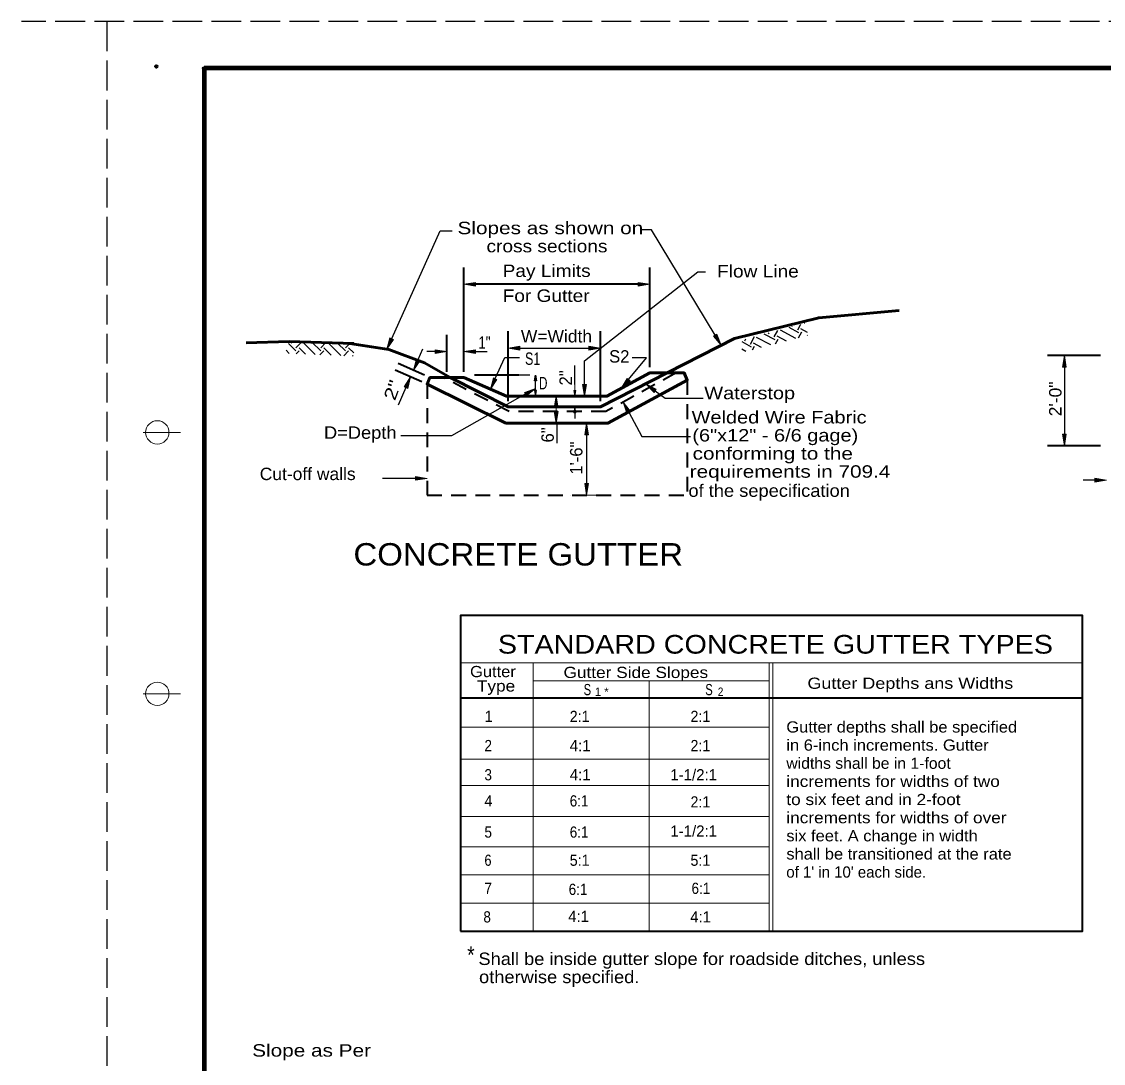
# Model space of a CAD drawing. Extents: x 72.6 to 107.3, y 36.1 to 58.1.
# Drawn here: x 72.62 to 84.21, y 46.92 to 58.08 of the extents above; entities that cross this region are included whole.
import ezdxf

# ---------------------------------------------------------------- set-up
doc = ezdxf.new("R2010")
doc.units = 0
doc.header["$LTSCALE"] = 0.053
doc.header["$PDMODE"] = 32
doc.header["$PDSIZE"] = 0.0265
doc.linetypes.add('LONG_DASHED', pattern=[7.5, 6, -1.5])
doc.linetypes.add('MEDIUM_DASHED', pattern=[4.5, 3, -1.5])
for name, color, linetype, lineweight in [('1', 7, 'Continuous', 35), ('2', 7, 'MEDIUM_DASHED', 35), ('3', 7, 'Continuous', 13), ('6', 7, 'Continuous', 13)]:
    doc.layers.add(name, color=color, linetype=linetype, lineweight=lineweight)

msp = doc.modelspace()

# ---------------------------------------------------------------- hatches: boundary and pattern name
at = {"layer": '1'}
for points in [[(77.48683, 55.24517), (77.48683, 55.28683), (77.36183, 55.266), (77.36183, 55.266)], [(79.23108, 55.24517), (79.23108, 55.28683), (79.35608, 55.266), (79.35608, 55.266)], [(77.96333, 54.56225), (77.96333, 54.60392), (77.83833, 54.58308), (77.83833, 54.58308)], [(78.70275, 54.56225), (78.70275, 54.60392), (78.82775, 54.58308), (78.82775, 54.58308)], [(76.89275, 54.45125), (76.85458, 54.468), (76.82333, 54.34517), (76.82333, 54.34517)], [(83.81583, 54.37842), (83.77408, 54.37842), (83.795, 54.50342), (83.795, 54.50342)], [(76.761, 54.15175), (76.72283, 54.1685), (76.79225, 54.2745), (76.79225, 54.2745)], [(78.13983, 54.23092), (78.119, 54.23092), (78.12942, 54.29342), (78.12942, 54.29342)], [(78.13983, 54.12917), (78.119, 54.12917), (78.12942, 54.06667), (78.12942, 54.06667)], [(78.56175, 54.12917), (78.54092, 54.12917), (78.55133, 54.06667), (78.55133, 54.06667)], [(78.372, 53.94167), (78.33033, 53.94167), (78.35117, 54.06667), (78.35117, 54.06667)], [(78.372, 53.90358), (78.33033, 53.90358), (78.35117, 53.77858), (78.35117, 53.77858)], [(78.56175, 53.89008), (78.54092, 53.89008), (78.55133, 53.95258), (78.55133, 53.95258)], [(78.69833, 53.65358), (78.65667, 53.65358), (78.6775, 53.77858), (78.6775, 53.77858)], [(83.81583, 53.65967), (83.77408, 53.65967), (83.795, 53.53467), (83.795, 53.53467)], [(78.69833, 53.13175), (78.65667, 53.13175), (78.6775, 53.00675), (78.6775, 53.00675)], [(84.12108, 53.14683), (84.12108, 53.1885), (84.24608, 53.16758), (84.24608, 53.16758)]]:
    msp.add_hatch(color=256, dxfattribs=at).paths.add_polyline_path(points)
at = {"layer": '3'}
for points in [[(80.072, 54.73067), (80.03633, 54.70917), (80.11867, 54.61283), (80.11867, 54.61283)], [(76.60825, 54.67558), (76.57025, 54.69267), (76.53808, 54.57008), (76.53808, 54.57008)], [(77.0555, 54.52408), (77.0555, 54.56575), (77.1805, 54.54492), (77.1805, 54.54492)], [(77.48683, 54.52408), (77.48683, 54.56575), (77.36183, 54.54492), (77.36183, 54.54492)], [(77.71708, 54.2475), (77.67908, 54.26467), (77.64675, 54.14208), (77.64675, 54.14208)], [(79.14242, 54.23167), (79.11033, 54.25833), (79.0465, 54.14883), (79.0465, 54.14883)], [(78.01033, 54.10767), (78.03083, 54.07142), (78.12942, 54.151), (78.12942, 54.151)], [(78.67658, 54.19167), (78.63492, 54.19167), (78.65575, 54.06667), (78.65575, 54.06667)], [(79.39933, 54.10883), (79.42408, 54.14233), (79.31117, 54.19983), (79.31117, 54.19983)], [(79.10992, 53.885), (79.14658, 53.90483), (79.06875, 54.00492), (79.06875, 54.00492)], [(76.84317, 53.20833), (76.84317, 53.16667), (76.96817, 53.1875), (76.96817, 53.1875)]]:
    msp.add_hatch(color=256, dxfattribs=at).paths.add_polyline_path(points)

# ---------------------------------------------------------------- linework, layer by layer
at = {"layer": '1', "linetype": 'LONG_DASHED', "lineweight": 25}
for p, q in [((107.16175, 58.07983), (72.62475, 58.07983)), ((73.53675, 58.07983), (73.53675, 36.07983))]:
    msp.add_line(p, q, dxfattribs=at)
at = {"layer": '1', "lineweight": 158}
for p, q in [((74.57842, 57.57983), (74.57842, 36.57983)), ((107.07842, 57.57983), (74.57842, 57.57983))]:
    msp.add_line(p, q, dxfattribs=at)
at = {"layer": '1'}
for p, q in [((77.36183, 54.33033), (77.36183, 55.446)), ((79.35608, 54.37925), (79.35608, 55.446)), ((79.23108, 55.266), (77.48683, 55.266)), ((77.83833, 54.01508), (77.83833, 54.76308)), ((78.82775, 54.01508), (78.82775, 54.76308)), ((84.18358, 54.50342), (83.615, 54.50342)), ((76.942, 54.293), (76.65858, 54.41767)), ((76.91092, 54.22233), (76.6275, 54.347)), ((84.18358, 53.53467), (83.615, 53.53467)), ((77.32617, 50.836), (83.98917, 50.836))]:
    msp.add_line(p, q, dxfattribs=at)
at = {"layer": '1', "lineweight": 25}
for p, q in [((80.94175, 54.7785), (80.97342, 54.83742)), ((81.01333, 54.84642), (81.01142, 54.8475)), ((80.43375, 54.62625), (80.47658, 54.70592)), ((80.65042, 54.616), (80.49875, 54.69767)), ((80.69725, 54.67067), (80.58067, 54.73342)), ((80.62575, 54.73575), (80.63192, 54.747)), ((80.68775, 54.70242), (80.725, 54.77167)), ((80.81792, 54.65883), (80.7195, 54.71192)), ((80.91783, 54.68492), (80.75275, 54.77383)), ((80.95125, 54.74683), (80.84575, 54.80358)), ((80.87975, 54.81192), (80.88033, 54.81275)), ((80.94842, 54.69225), (80.983, 54.75633)), ((81.04183, 54.75125), (80.9735, 54.78808)), ((81.04108, 54.716), (81.04483, 54.723)), ((75.56342, 54.55242), (75.48217, 54.63358)), ((75.51367, 54.63525), (75.53108, 54.65258)), ((75.56342, 54.5855), (75.62733, 54.6495)), ((75.66442, 54.51767), (75.59658, 54.5855)), ((75.76808, 54.5135), (75.64625, 54.63525)), ((75.82858, 54.55242), (75.735, 54.646)), ((75.77883, 54.63525), (75.78792, 54.64425)), ((75.82858, 54.5855), (75.88417, 54.64117)), ((75.94083, 54.50642), (75.86175, 54.5855)), ((76.044, 54.50267), (75.91142, 54.63525)), ((76.09375, 54.55242), (76.009, 54.63708)), ((76.044, 54.63525), (76.04475, 54.63592)), ((76.09375, 54.5855), (76.141, 54.63283)), ((76.18183, 54.53058), (76.12692, 54.5855)), ((76.18183, 54.63), (76.18033, 54.63158)), ((77.96333, 54.58308), (78.70275, 54.58308)), ((80.44325, 54.5945), (80.34208, 54.64892)), ((80.37175, 54.65958), (80.3835, 54.68117)), ((80.45442, 54.56592), (80.475, 54.60408)), ((80.54992, 54.59025), (80.4655, 54.63575)), ((80.70142, 54.62908), (80.729, 54.68025)), ((75.49158, 54.52475), (75.45717, 54.55917)), ((75.56592, 54.52175), (75.59658, 54.55242)), ((75.82067, 54.51133), (75.86175, 54.55242)), ((76.07542, 54.50092), (76.12692, 54.55242)), ((76.171, 54.49708), (76.17658, 54.50267)), ((76.87367, 54.45958), (76.924, 54.574)), ((80.38233, 54.54742), (80.3395, 54.5705)), ((78.55133, 54.19167), (78.55133, 54.39708)), ((83.795, 54.37842), (83.795, 53.65967)), ((78.06983, 54.29342), (77.94942, 54.29342)), ((76.74192, 54.16008), (76.65842, 53.97025)), ((78.12942, 54.12917), (78.12942, 54.23092)), ((78.077, 54.06667), (77.94942, 54.06667)), ((78.55133, 53.89008), (78.55133, 53.82758)), ((78.56908, 53.77858), (78.8575, 53.77858)), ((78.6775, 53.65358), (78.6775, 53.13175)), ((84.12108, 53.16767), (83.99608, 53.16767))]:
    msp.add_line(p, q, dxfattribs=at)
at = {"layer": '1', "lineweight": 53}
for p, q in [((75.48908, 54.654), (75.0305, 54.63792)), ((76.18183, 54.6315), (75.48908, 54.654)), ((76.55892, 54.56683), (76.141, 54.63283))]:
    msp.add_line(p, q, dxfattribs=at)
at = {"layer": '1', "lineweight": 13}
for p, q in [((78.55133, 54.12917), (78.55133, 54.19167)), ((78.39292, 54.06667), (78.53117, 54.06667)), ((78.61233, 54.06667), (78.73133, 54.06667)), ((78.35117, 53.94167), (78.35117, 53.90358)), ((78.61383, 53.95258), (78.73133, 53.95258)), ((78.40333, 53.77858), (78.53117, 53.77858)), ((74.32842, 53.67983), (73.92842, 53.67983)), ((78.56908, 53.00675), (78.8575, 53.00675)), ((77.32617, 51.213), (83.98917, 51.213)), ((78.10642, 51.213), (78.10642, 48.33683)), ((80.632, 48.33683), (80.632, 51.213)), ((80.67308, 48.33683), (80.67308, 51.213)), ((78.10642, 51.01908), (80.632, 51.01908)), ((79.34867, 51.01908), (79.34867, 48.33683)), ((74.32842, 50.87983), (73.92842, 50.87983)), ((77.32617, 50.52358), (80.632, 50.52358)), ((77.32617, 50.17883), (80.632, 50.17883)), ((77.32617, 49.89875), (80.632, 49.89875)), ((77.32617, 49.56483), (80.632, 49.56483)), ((77.32617, 49.24158), (80.632, 49.24158)), ((77.32617, 48.94), (80.632, 48.94)), ((77.32617, 48.63842), (80.632, 48.63842))]:
    msp.add_line(p, q, dxfattribs=at)
for points in [[(77.48683, 55.24517), (77.48683, 55.28683), (77.36183, 55.266), (77.36183, 55.266)], [(79.23108, 55.24517), (79.23108, 55.28683), (79.35608, 55.266), (79.35608, 55.266)], [(77.96333, 54.56225), (77.96333, 54.60392), (77.83833, 54.58308), (77.83833, 54.58308)], [(78.70275, 54.56225), (78.70275, 54.60392), (78.82775, 54.58308), (78.82775, 54.58308)], [(76.89275, 54.45125), (76.85458, 54.468), (76.82333, 54.34517), (76.82333, 54.34517)], [(83.81583, 54.37842), (83.77408, 54.37842), (83.795, 54.50342), (83.795, 54.50342)], [(76.761, 54.15175), (76.72283, 54.1685), (76.79225, 54.2745), (76.79225, 54.2745)], [(78.56175, 54.12917), (78.54092, 54.12917), (78.55133, 54.06667), (78.55133, 54.06667)], [(78.372, 53.94167), (78.33033, 53.94167), (78.35117, 54.06667), (78.35117, 54.06667)], [(78.372, 53.90358), (78.33033, 53.90358), (78.35117, 53.77858), (78.35117, 53.77858)], [(78.56175, 53.89008), (78.54092, 53.89008), (78.55133, 53.95258), (78.55133, 53.95258)], [(78.69833, 53.65358), (78.65667, 53.65358), (78.6775, 53.77858), (78.6775, 53.77858)], [(83.81583, 53.65967), (83.77408, 53.65967), (83.795, 53.53467), (83.795, 53.53467)], [(78.69833, 53.13175), (78.65667, 53.13175), (78.6775, 53.00675), (78.6775, 53.00675)], [(84.12108, 53.14683), (84.12108, 53.1885), (84.24608, 53.16758), (84.24608, 53.16758)]]:
    msp.add_lwpolyline(points, close=True, dxfattribs=at)
at = {"layer": '1', "lineweight": 53}
for points in [[(80.2625, 54.68642), (81.16475, 54.908), (82.02408, 54.98392)], [(80.2625, 54.68642), (78.82775, 53.95258), (77.83833, 53.95258), (77.21675, 54.26783), (76.94225, 54.4255), (76.55892, 54.56683)]]:
    msp.add_lwpolyline(points, dxfattribs=at)
msp.add_lwpolyline([(77.8125, 53.77858), (78.90542, 53.77858), (79.75492, 54.24067), (79.72383, 54.31675), (79.35608, 54.31675), (78.89508, 54.06667), (77.81767, 54.06667), (77.36183, 54.26783), (76.99925, 54.26783), (76.96817, 54.19717)], close=True, dxfattribs=at)
at = {"layer": '1', "lineweight": 25}
for points in [[(78.13983, 54.23092), (78.119, 54.23092), (78.12942, 54.29342), (78.12942, 54.29342)], [(78.13983, 54.12917), (78.119, 54.12917), (78.12942, 54.06667), (78.12942, 54.06667)]]:
    msp.add_lwpolyline(points, close=True, dxfattribs=at)
at = {"layer": '1'}
msp.add_lwpolyline([(77.32617, 48.33683), (83.98917, 48.33683), (83.98917, 51.71933), (77.32617, 51.71933)], close=True, dxfattribs=at)
at = {"layer": '1', "lineweight": 13}
for centre in [(74.07842, 53.67983), (74.07842, 50.87983)]:
    msp.add_circle(centre, 0.125, dxfattribs=at)
at = {"layer": '1'}
for p in [(74.06642, 57.59983), (74.57842, 57.57983)]:
    msp.add_point(p, dxfattribs=at)
at = {"layer": '2'}
for p, q in [((79.75492, 54.24067), (79.75492, 53.00675)), ((76.96817, 54.19717), (76.96817, 53.00675)), ((76.96817, 53.00675), (79.75492, 53.00675))]:
    msp.add_line(p, q, dxfattribs=at)
msp.add_lwpolyline([(79.63575, 54.31675), (78.88467, 53.90367), (77.84875, 53.90367), (77.13908, 54.26783)], dxfattribs=at)
at = {"layer": '3', "lineweight": 35}
for p, q in [((77.1805, 54.33033), (77.1805, 54.72492)), ((77.94942, 54.29342), (77.47467, 54.29342))]:
    msp.add_line(p, q, dxfattribs=at)
at = {"layer": '3'}
for p, q in [((77.36183, 54.49833), (77.36183, 54.72492)), ((77.1805, 54.54492), (77.18058, 54.54492))]:
    msp.add_line(p, q, dxfattribs=at)
at = {"layer": '3', "lineweight": 25}
for p, q in [((77.0555, 54.54492), (76.96517, 54.54492)), ((77.48683, 54.54492), (77.61183, 54.54492)), ((79.41175, 54.12558), (79.52025, 54.0455)), ((79.52025, 54.0455), (79.92517, 54.0455)), ((78.35892, 53.77858), (78.35892, 53.56333)), ((76.84317, 53.1875), (76.48908, 53.1875))]:
    msp.add_line(p, q, dxfattribs=at)
for points in [[(76.58925, 54.68417), (77.10775, 55.8385), (77.23775, 55.8385)], [(80.05417, 54.71992), (79.37358, 55.85033), (79.26058, 55.85033)], [(78.65575, 54.19167), (78.65575, 54.44792), (79.86908, 55.39933), (79.94992, 55.39933)], [(77.69808, 54.25608), (77.79975, 54.48167), (77.95692, 54.48167)], [(79.12642, 54.245), (79.32017, 54.47825), (79.16417, 54.47825)], [(78.02058, 54.0895), (77.22858, 53.642), (76.6855, 53.642)], [(79.12825, 53.89492), (79.26817, 53.63592), (79.78917, 53.63592)]]:
    msp.add_lwpolyline(points, dxfattribs=at)
at = {"layer": '3'}
for points in [[(80.072, 54.73067), (80.03633, 54.70917), (80.11867, 54.61283), (80.11867, 54.61283)], [(76.60825, 54.67558), (76.57025, 54.69267), (76.53808, 54.57008), (76.53808, 54.57008)], [(77.0555, 54.52408), (77.0555, 54.56575), (77.1805, 54.54492), (77.1805, 54.54492)], [(77.48683, 54.52408), (77.48683, 54.56575), (77.36183, 54.54492), (77.36183, 54.54492)], [(77.71708, 54.2475), (77.67908, 54.26467), (77.64675, 54.14208), (77.64675, 54.14208)], [(79.14242, 54.23167), (79.11033, 54.25833), (79.0465, 54.14883), (79.0465, 54.14883)], [(78.01033, 54.10767), (78.03083, 54.07142), (78.12942, 54.151), (78.12942, 54.151)], [(78.67658, 54.19167), (78.63492, 54.19167), (78.65575, 54.06667), (78.65575, 54.06667)], [(79.39933, 54.10883), (79.42408, 54.14233), (79.31117, 54.19983), (79.31117, 54.19983)], [(79.10992, 53.885), (79.14658, 53.90483), (79.06875, 54.00492), (79.06875, 54.00492)], [(76.84317, 53.20833), (76.84317, 53.16667), (76.96817, 53.1875), (76.96817, 53.1875)]]:
    msp.add_lwpolyline(points, close=True, dxfattribs=at)
at = {"layer": '6'}
for p, q in [((77.36183, 55.266), (77.36192, 55.266)), ((78.82775, 54.58308), (78.82783, 54.58308)), ((77.36183, 54.43583), (77.36192, 54.43583)), ((76.82333, 54.34517), (76.82342, 54.34517)), ((76.99925, 54.26783), (76.99933, 54.26783)), ((77.1805, 54.26783), (77.18058, 54.26783)), ((77.36183, 54.26783), (77.36192, 54.26783)), ((79.35608, 54.31675), (79.35617, 54.31675)), ((76.96817, 54.19717), (76.96825, 54.19717)), ((78.33042, 54.06667), (78.3305, 54.06667)), ((78.54983, 54.06667), (78.54992, 54.06667)), ((78.55133, 54.06667), (78.55142, 54.06667)), ((77.83833, 53.95258), (77.83842, 53.95258)), ((78.55133, 53.95258), (78.55142, 53.95258)), ((78.82775, 53.95258), (78.82783, 53.95258)), ((78.34083, 53.77858), (78.34092, 53.77858)), ((78.35117, 53.77858), (78.35125, 53.77858)), ((78.50658, 53.77858), (78.50667, 53.77858)), ((83.795, 53.53467), (83.79508, 53.53467)), ((78.50658, 53.00675), (78.50667, 53.00675)), ((78.6775, 53.00675), (78.67758, 53.00675))]:
    msp.add_line(p, q, dxfattribs=at)
at = {"layer": '6', "lineweight": 25}
for p, q in [((78.12942, 54.29342), (78.1295, 54.29342)), ((78.13233, 54.29342), (78.13242, 54.29342)), ((78.1395, 54.06667), (78.13958, 54.06667))]:
    msp.add_line(p, q, dxfattribs=at)

# ---------------------------------------------------------------- texts
at = {"layer": '1', "width": 1.05}
msp.add_text('W=Width', height=0.133, dxfattribs=at).set_placement((77.97308, 54.64308))
at = {"layer": '1'}
for s, p in [('2"', (78.51933, 54.18267)), ('1\'-6"', (78.63208, 53.22725))]:
    msp.add_text(s, height=0.133, rotation=90, dxfattribs=at).set_placement(p)
at = {"layer": '1', "width": 1.05}
msp.add_text('2\'-0"', height=0.133, rotation=90, dxfattribs=at).set_placement((83.76467, 53.85267))
at = {"layer": '3'}
for s, height, width, p in [('Slopes as shown on', 0.133, 1.25, (77.29425, 55.80292)), ('cross sections', 0.133, 1.15, (77.605, 55.60858)), ('Pay Limits', 0.133, 1.15, (77.7775, 55.34475)), ('Flow Line', 0.133, 1.15, (80.07492, 55.33933)), ('For Gutter', 0.133, 1.15, (77.7775, 55.07775)), ('1"', 0.133, 0.8, (77.518, 54.57533)), ('S1', 0.133, 0.75, (78.01775, 54.40333)), ('D', 0.133, 0.7, (78.16767, 54.14083)), ('Waterstop', 0.133, 1.2, (79.93808, 54.03492)), ('Welded Wire Fabric ', 0.133, 1.2, (79.80258, 53.77542)), ('D=Depth', 0.133, 1.1, (75.86375, 53.61125)), ('(6"x12" - 6/6 gage)', 0.133, 1.2, (79.81, 53.5825)), ('conforming to the ', 0.133, 1.25, (79.81258, 53.38783)), ('Cut-off walls', 0.133, 1.05, (75.17558, 53.16892)), (' requirements in 709.4 ', 0.133, 1.25, (79.71967, 53.1945)), (' of the sepecification', 0.133, 1.1, (79.71392, 52.98933)), ('CONCRETE GUTTER', 0.24, 1.1, (76.17925, 52.25367)), ('STANDARD CONCRETE GUTTER TYPES', 0.2, 1.15, (77.72658, 51.31)), ('Gutter', 0.12, 1.1, (77.42842, 51.05808)), ('Gutter Side Slopes', 0.12, 1.15, (78.43008, 51.04875)), ('Type', 0.12, 1.15, (77.50183, 50.904)), ('Gutter Depths ans Widths', 0.12, 1.2, (81.04267, 50.93292)), ('S', 0.12, 0.75, (78.64525, 50.86483)), ('S', 0.12, 0.75, (79.94825, 50.86483)), ('2', 0.09, 0.9, (80.08225, 50.85625)), ('2:1', 0.12, 0.95, (78.49658, 50.57742)), ('2:1', 0.12, 0.95, (79.79017, 50.57742)), ('Gutter depths shall be specified', 0.12, 1.1, (80.81675, 50.46467)), ('2', 0.12, 0.9, (77.58283, 50.265)), ('2:1', 0.12, 0.95, (79.79017, 50.265)), ('in 6-inch increments. Gutter', 0.12, 1.1, (80.81675, 50.27042)), ('widths shall be in 1-foot', 0.12, 1.05, (80.81675, 50.07608)), ('3', 0.12, 0.9, (77.58283, 49.95258)), ('increments for widths of two', 0.12, 1.15, (80.81675, 49.88183)), ('4', 0.12, 0.95, (77.58283, 49.6725)), ('6:1', 0.12, 0.9, (78.49658, 49.6725)), ('2:1', 0.12, 0.95, (79.79017, 49.66175)), ('to six feet and in 2-foot', 0.12, 1.15, (80.81675, 49.68758)), ('increments for widths of over', 0.12, 1.15, (80.81675, 49.49325)), ('5', 0.12, 0.9, (77.58283, 49.33858)), ('6:1', 0.12, 0.9, (78.49658, 49.33858)), ('six feet. A change in width', 0.12, 1.1, (80.81675, 49.299)), ('6', 0.12, 0.85, (77.58283, 49.03692)), ('5:1', 0.12, 0.95, (78.49658, 49.03692)), ('5:1', 0.12, 0.95, (79.79017, 49.03692)), ('shall be transitioned at the rate', 0.12, 1.1, (80.81675, 49.10467)), ('7', 0.12, 0.9, (77.58283, 48.73633)), ('6:1', 0.12, 0.9, (78.48542, 48.72525)), ('6:1', 0.12, 0.9, (79.80133, 48.73633)), ('8', 0.12, 0.9, (77.57167, 48.43017)), ('*', 0.18, 0.85, (77.398, 47.99317)), ('Shall be inside gutter slope for roadside ditches, unless', 0.133, 1.1, (77.51808, 47.97458)), ('otherwise specified.', 0.133, 1.1, (77.52483, 47.78025)), (' Slope as Per ', 0.133, 1.25, (75.03283, 46.99317))]:
    msp.add_text(s, height=height, dxfattribs=dict(at, width=width)).set_placement(p)
for s, height, p in [('S2', 0.133, (78.91825, 54.42742)), ('1 *', 0.09, (78.76592, 50.85625)), ('1', 0.12, (77.58283, 50.57742)), ('4:1', 0.12, (78.49658, 50.265)), ('4:1', 0.12, (78.49658, 49.95258)), ('1-1/2:1', 0.12, (79.5745, 49.95258)), ('1-1/2:1', 0.12, (79.5745, 49.34933)), ("of 1' in 10' each side.", 0.12, (80.81675, 48.91042)), ('4:1', 0.12, (78.47983, 48.43583)), ('4:1', 0.12, (79.78683, 48.43033))]:
    msp.add_text(s, height=height, dxfattribs=at).set_placement(p)
at = {"layer": '3', "width": 1.3}
msp.add_text('2"', height=0.133, rotation=70, dxfattribs=at).set_placement((76.6235, 54.01158))
at = {"layer": '3'}
msp.add_text('6"', height=0.133, rotation=90, dxfattribs=at).set_placement((78.32567, 53.57183))

doc.saveas('drawing.dxf')
